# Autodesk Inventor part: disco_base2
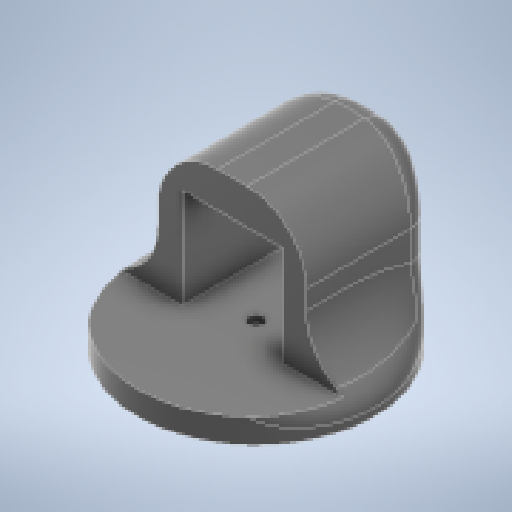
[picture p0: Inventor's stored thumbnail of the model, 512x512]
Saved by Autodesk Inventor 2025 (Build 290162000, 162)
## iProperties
Created: 2026-03
Part Number: disco_base2
Material: Plastica ABS
Document SubType Name: Modeling
Designer: R5800u
Density: 1.06 g/cm^3
Appearance: Liscia - Nero
Author: R5800u
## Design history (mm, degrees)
sketch "Schizzo1"
  geometry: C1 r 50 at (0, 0); 1 further point
  constraints: 1 centre point, 1 coincident
  dimensions: "d0" = 100 diameter of C1
extrude "Estrusione1" new body sketch "Schizzo1" distance "d1" = 10; taper "d2" = 0 deg
sketch "Schizzo2"
  geometry: C1 r 50 at (0, 0) reference; 3 further points
  constraints: 1 coincident
hole "Foro1" sketch "Schizzo2" at (0, 0) diameter "d3" = 3.4; stored, may be unused: countersink angle "d7" = 82 deg, drill point angle "d9" = 118 deg; dims "d4" = 6, "d5" = 6.5, "d6" = 3.4, "d8" = 8
sketch "Schizzo4"
  geometry: C1 r 1.6 at (-55, 30) reference; C2 r 1.6 at (-55, -30) reference; C3 r 1.6 at (55, -30) reference; C4 r 1.6 at (55, 30) reference; 1 further point
hole "Foro2" sketch "Schizzo4" at (-55, 30), (-55, -30), (55, 30), (55, -30) diameter "d14" = 4.3; stored, may be unused: countersink angle "d18" = 90 deg, drill point angle "d20" = 118 deg; dims "d15" = 6, "d16" = 7.5, "d17" = 3, "d19" = 8
sketch "Schizzo5"
  geometry: L1 (0, 0)-(0, -50); L2 (-21.2, -45.283)-(-21.2, 45.283); L3 (-21.2, -10)-(0, -10); L4 (21.2, -45.283)-(21.2, 45.283); L5 (21.2, -10)-(0, -10); L6 (-21.2, 45.283)-(21.2, 45.283); L7 (-31.2, -45.283)-(-31.2, 55.283); L8 (-31.2, 55.283)-(31.2, 55.283); L9 (31.2, 55.283)-(31.2, -45.283); L10 (-31.2, -10)-(31.2, -10); C1 r 1.7 at (0, 0) reference; A1 r 50 centre (0, 0) between (0, -50) and (-21.2, 45.283) reference; 7 further points
  constraints: 20 end point, 5 point on line, 3 point on circle, 3 symmetric about line, 2 perpendicular, 2 vertical, 1 horizontal, 2 other
  dimensions: "d22" = 21.2 distance between parallel lines of L1 L2; "d23" = 10 distance from line of point (0, 0) L3; "d24" = 10 distance between parallel lines of L2 L7
extrude "Estrusione3" join sketch "Schizzo5" distance "d25" = 42.2; taper "d26" = 0 deg
sketch "Schizzo6"
  geometry: L1 (31.2, -10)-(31.2, 39.071) reference; L2 (21.2, 45.283)-(21.2, -10) reference; L3 (21.2, -10)-(31.2, -10) reference; L4 (-21.2, -10)-(-21.2, 45.283) reference; L5 (-31.2, 39.071)-(-31.2, -10) reference; L6 (-31.2, -10)-(-21.2, -10) reference; L7 (21.2, -10)-(-21.2, -10); A1 r 50 centre (0, 0) between (31.2, 39.071) and (21.2, 45.283) reference; A2 r 50 centre (0, 0) between (21.2, 45.283) and (-21.2, 45.283) reference; A3 r 50 centre (0, 0) between (-21.2, 45.283) and (-31.2, 39.071) reference; 2 further points
  constraints: 2 end point, 1 horizontal
extrude "Estrusione4" join sketch "Schizzo6" distance "d27" = 15; taper "d28" = 0 deg
fillet "Raccordo3" dims "d29" = 25
fillet "Raccordo4" dims "d30" = 10
sketch "Schizzo7"
  geometry: C1 r 1.229 at (21.2, 21) reference; C2 r 5 at (21.2, 21); C3 r 1.621 at (21.2, 36) reference; C4 r 1.621 at (36.2, 21) reference; C5 r 1.621 at (6.2, 21) reference; C6 r 1.621 at (21.2, 6) reference; 1 further point
  constraints: 1 centre point, 1 coincident
  dimensions: "d31" = 10 diameter of C2
extrude "Estrusione5" cut sketch "Schizzo7" extent not by distance; stored distance "d32" = 0; taper "d33" = 0 deg
node "Solido1"
node "Riferimento5"
node "Riferimento6"
node "Riferimento7"
node "Riferimento8"
node "Linea chiusa proiettata2"
node "Linea chiusa proiettata3"
node "Riferimento9"
node "Riferimento10"
node "Riferimento11"
node "Riferimento12"
node "Riferimento13"
